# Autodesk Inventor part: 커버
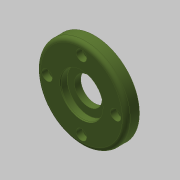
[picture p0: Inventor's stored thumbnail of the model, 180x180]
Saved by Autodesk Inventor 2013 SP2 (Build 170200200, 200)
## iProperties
Created: 2016-06
Part Number: 커버
Material: 알루미늄 6061
Document SubType Name: Modeling
Designer: mduedu
Density: 2.71 g/cm^3
Author: mduedu
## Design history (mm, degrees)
sketch "스케치1"
  geometry: C1 r 34 at (0, 0); 1 further point
  constraints: 1 centre point, 1 coincident
  dimensions: "d0" = 68 diameter of C1
extrude "돌출1" new body sketch "스케치1" distance "d2" = 10; taper "d3" = 0 deg
sketch "스케치2"
  geometry: C1 r 21 at (0, 0); 1 further point
  constraints: 1 centre point, 1 coincident
  dimensions: "d4" = 42 diameter of C1
extrude "돌출2" join sketch "스케치2" distance "d6" = 3; taper "d7" = 0 deg
fillet "모깎기1" dims "d8" = 3
hole "구멍1" diameter "d11" = 35; stored, may be unused: countersink angle "d15" = 90 deg, drill point angle "d17" = 0 deg; dims "d9" = 10, "d10" = 10, "d12" = 6, "d13" = 4, "d14" = 2, "d16" = 3
hole "구멍2" diameter "d20" = 32; stored, may be unused: countersink angle "d24" = 90 deg, drill point angle "d26" = 0 deg; dims "d21" = 6, "d22" = 4, "d23" = 2, "d25" = 5.2, "d46" = 10, "d47" = 10
hole "구멍3" diameter "d29" = 21; stored, may be unused: countersink angle "d33" = 90 deg, drill point angle "d35" = 0 deg; dims "d27" = 10, "d28" = 10, "d30" = 6, "d31" = 4, "d32" = 2, "d34" = 5
fillet "모깎기2" dims "d36" = 3
fillet "모깎기3" dims "d37" = 0.1
chamfer "모따기1" distance "d38" = 0.75; stored, may be unused: second distance "d39" = 2, angle "d40" = 30 deg
chamfer "모따기2" distance "d42" = 0.5; stored, may be unused: second distance "d43" = 2, angle "d44" = 30 deg
sketch "스케치3" dims "d48" = 52
  geometry: 6 further points
  constraints: 2 vertical alignment, 1 coincident, 7 other
  dimensions: "d51" = 360 deg dimension on point (0, 0) point (0, 26) (derived)
sketch "스케치4"
  geometry: 4 further points
hole "구멍4" sketch "스케치4" at (0, 26), (-26, 0), (0, -26), (26, 0) diameter "d53" = 4.5; stored, may be unused: countersink angle "d57" = 90 deg, drill point angle "d59" = 0 deg; dims "d54" = 6, "d55" = 8, "d56" = 4.6, "d58" = 8
node "솔리드1"
